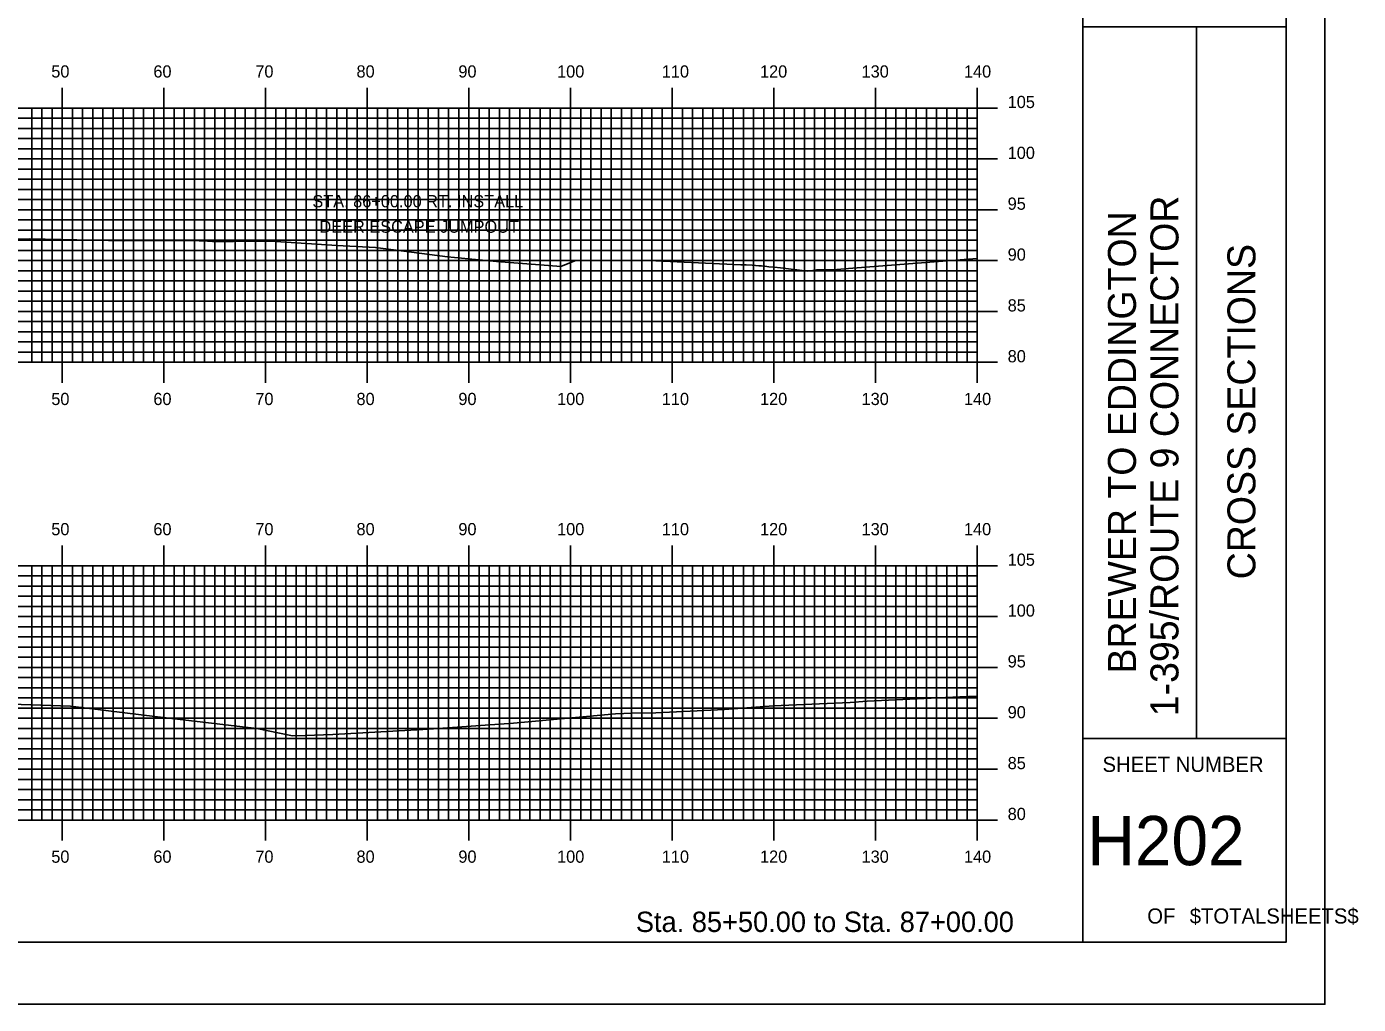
# Model space of a CAD drawing. Extents: x 1763759 to 1764102, y 442591 to 442811.
# Drawn here: x 1763970.8 to 1764101.8, y 442590.5 to 442686.7 of the extents above; entities that cross this region are included whole.
import ezdxf

# ---------------------------------------------------------------- set-up
doc = ezdxf.new("R2010")
doc.units = 0
for name, color, linetype in [('BORDER', 7, 'Continuous'), ('D_Text_Standard', 7, 'Continuous'), ('H_V ANNOTATION', 7, 'Continuous'), ('MAJOR', 7, 'Continuous'), ('MINOR', 7, 'Continuous'), ('PLOT BOUNDARY', 7, 'Continuous'), ('S_Roadway_Centerline', 7, 'Continuous')]:
    doc.layers.add(name, color=color, linetype=linetype)

msp = doc.modelspace()

# ---------------------------------------------------------------- linework, layer by layer
at = {"layer": 'BORDER'}
for p, q in [((1764074.72, 442596.67), (1764074.72, 442806.67)), ((1764074.72, 442686.67), (1764094.72, 442686.67)), ((1764085.9, 442616.67), (1764085.9, 442686.67)), ((1764074.72, 442616.67), (1764094.72, 442616.67))]:
    msp.add_line(p, q, dxfattribs=at)
msp.add_lwpolyline([(1763774.72, 442596.67), (1764094.72, 442596.67), (1764094.72, 442806.67), (1763774.72, 442806.67)], close=True, dxfattribs=at)
at = {"layer": 'MAJOR'}
for p, q in [((1763974.32, 442680.67), (1763974.32, 442678.67)), ((1763984.32, 442680.67), (1763984.32, 442678.67)), ((1763994.32, 442680.67), (1763994.32, 442678.67)), ((1764004.32, 442680.67), (1764004.32, 442678.67)), ((1764014.32, 442680.67), (1764014.32, 442678.67)), ((1764024.32, 442680.67), (1764024.32, 442678.67)), ((1764034.32, 442680.67), (1764034.32, 442678.67)), ((1764044.32, 442680.67), (1764044.32, 442678.67)), ((1764054.32, 442680.67), (1764054.32, 442678.67)), ((1764064.32, 442680.67), (1764064.32, 442678.67)), ((1763784.32, 442678.67), (1764064.32, 442678.67)), ((1763784.32, 442678.67), (1764064.32, 442678.67)), ((1763974.32, 442653.67), (1763974.32, 442678.67)), ((1763984.32, 442653.67), (1763984.32, 442678.67)), ((1763994.32, 442653.67), (1763994.32, 442678.67)), ((1764004.32, 442653.67), (1764004.32, 442678.67)), ((1764014.32, 442653.67), (1764014.32, 442678.67)), ((1764024.32, 442653.67), (1764024.32, 442678.67)), ((1764034.32, 442653.67), (1764034.32, 442678.67)), ((1764044.32, 442653.67), (1764044.32, 442678.67)), ((1764054.32, 442653.67), (1764054.32, 442678.67)), ((1764066.32, 442678.67), (1764062.31, 442678.67)), ((1764064.32, 442653.67), (1764064.32, 442678.67)), ((1764064.32, 442653.67), (1764064.32, 442678.67)), ((1763784.32, 442673.67), (1764064.32, 442673.67)), ((1764066.32, 442673.67), (1764062.31, 442673.67)), ((1763784.32, 442668.67), (1764064.32, 442668.67)), ((1764066.32, 442668.67), (1764062.31, 442668.67)), ((1763784.32, 442663.67), (1764064.32, 442663.67)), ((1764066.32, 442663.67), (1764062.31, 442663.67)), ((1763784.32, 442658.67), (1764064.32, 442658.67)), ((1764066.32, 442658.67), (1764062.31, 442658.67)), ((1763784.32, 442653.67), (1764064.32, 442653.67)), ((1763784.32, 442653.67), (1764064.32, 442653.67)), ((1763974.32, 442651.66), (1763974.32, 442653.67)), ((1763984.32, 442651.66), (1763984.32, 442653.67)), ((1763994.32, 442651.66), (1763994.32, 442653.67)), ((1764004.32, 442651.66), (1764004.32, 442653.67)), ((1764014.32, 442651.66), (1764014.32, 442653.67)), ((1764024.32, 442651.66), (1764024.32, 442653.67)), ((1764034.32, 442651.66), (1764034.32, 442653.67)), ((1764044.32, 442651.66), (1764044.32, 442653.67)), ((1764054.32, 442651.66), (1764054.32, 442653.67)), ((1764066.32, 442653.67), (1764062.31, 442653.67)), ((1764064.32, 442651.66), (1764064.32, 442653.67)), ((1763974.32, 442635.67), (1763974.32, 442633.67)), ((1763984.32, 442635.67), (1763984.32, 442633.67)), ((1763994.32, 442635.67), (1763994.32, 442633.67)), ((1764004.32, 442635.67), (1764004.32, 442633.67)), ((1764014.32, 442635.67), (1764014.32, 442633.67)), ((1764024.32, 442635.67), (1764024.32, 442633.67)), ((1764034.32, 442635.67), (1764034.32, 442633.67)), ((1764044.32, 442635.67), (1764044.32, 442633.67)), ((1764054.32, 442635.67), (1764054.32, 442633.67)), ((1764064.32, 442635.67), (1764064.32, 442633.67)), ((1763784.32, 442633.67), (1764064.32, 442633.67)), ((1763784.32, 442633.67), (1764064.32, 442633.67)), ((1763974.32, 442608.67), (1763974.32, 442633.67)), ((1763984.32, 442608.67), (1763984.32, 442633.67)), ((1763994.32, 442608.67), (1763994.32, 442633.67)), ((1764004.32, 442608.67), (1764004.32, 442633.67)), ((1764014.32, 442608.67), (1764014.32, 442633.67)), ((1764024.32, 442608.67), (1764024.32, 442633.67)), ((1764034.32, 442608.67), (1764034.32, 442633.67)), ((1764044.32, 442608.67), (1764044.32, 442633.67)), ((1764054.32, 442608.67), (1764054.32, 442633.67)), ((1764066.32, 442633.67), (1764062.31, 442633.67)), ((1764064.32, 442608.67), (1764064.32, 442633.67)), ((1764064.32, 442608.67), (1764064.32, 442633.67)), ((1763784.32, 442628.67), (1764064.32, 442628.67)), ((1764066.32, 442628.67), (1764062.31, 442628.67)), ((1763784.32, 442623.67), (1764064.32, 442623.67)), ((1764066.32, 442623.67), (1764062.31, 442623.67)), ((1763784.32, 442618.67), (1764064.32, 442618.67)), ((1764066.32, 442618.67), (1764062.31, 442618.67)), ((1763784.32, 442613.67), (1764064.32, 442613.67)), ((1764066.32, 442613.67), (1764062.31, 442613.67)), ((1763784.32, 442608.67), (1764064.32, 442608.67)), ((1763784.32, 442608.67), (1764064.32, 442608.67)), ((1763974.32, 442606.66), (1763974.32, 442608.67)), ((1763984.32, 442606.66), (1763984.32, 442608.67)), ((1763994.32, 442606.66), (1763994.32, 442608.67)), ((1764004.32, 442606.66), (1764004.32, 442608.67)), ((1764014.32, 442606.66), (1764014.32, 442608.67)), ((1764024.32, 442606.66), (1764024.32, 442608.67)), ((1764034.32, 442606.66), (1764034.32, 442608.67)), ((1764044.32, 442606.66), (1764044.32, 442608.67)), ((1764054.32, 442606.66), (1764054.32, 442608.67)), ((1764066.32, 442608.67), (1764062.31, 442608.67)), ((1764064.32, 442606.66), (1764064.32, 442608.67))]:
    msp.add_line(p, q, dxfattribs=at)
at = {"layer": 'MINOR'}
for p, q in [((1763971.32, 442653.67), (1763971.32, 442678.67)), ((1763972.32, 442653.67), (1763972.32, 442678.67)), ((1763973.32, 442653.67), (1763973.32, 442678.67)), ((1763975.32, 442653.67), (1763975.32, 442678.67)), ((1763976.32, 442653.67), (1763976.32, 442678.67)), ((1763977.32, 442653.67), (1763977.32, 442678.67)), ((1763978.32, 442653.67), (1763978.32, 442678.67)), ((1763979.32, 442653.67), (1763979.32, 442678.67)), ((1763980.32, 442653.67), (1763980.32, 442678.67)), ((1763981.32, 442653.67), (1763981.32, 442678.67)), ((1763982.32, 442653.67), (1763982.32, 442678.67)), ((1763983.32, 442653.67), (1763983.32, 442678.67)), ((1763985.32, 442653.67), (1763985.32, 442678.67)), ((1763986.32, 442653.67), (1763986.32, 442678.67)), ((1763987.32, 442653.67), (1763987.32, 442678.67)), ((1763988.32, 442653.67), (1763988.32, 442678.67)), ((1763989.32, 442653.67), (1763989.32, 442678.67)), ((1763990.32, 442653.67), (1763990.32, 442678.67)), ((1763991.32, 442653.67), (1763991.32, 442678.67)), ((1763992.32, 442653.67), (1763992.32, 442678.67)), ((1763993.32, 442653.67), (1763993.32, 442678.67)), ((1763995.32, 442653.67), (1763995.32, 442678.67)), ((1763996.32, 442653.67), (1763996.32, 442678.67)), ((1763997.32, 442653.67), (1763997.32, 442678.67)), ((1763998.32, 442653.67), (1763998.32, 442678.67)), ((1763999.32, 442653.67), (1763999.32, 442678.67)), ((1764000.32, 442653.67), (1764000.32, 442678.67)), ((1764001.32, 442653.67), (1764001.32, 442678.67)), ((1764002.32, 442653.67), (1764002.32, 442678.67)), ((1764003.32, 442653.67), (1764003.32, 442678.67)), ((1764005.32, 442653.67), (1764005.32, 442678.67)), ((1764006.32, 442653.67), (1764006.32, 442678.67)), ((1764007.32, 442653.67), (1764007.32, 442678.67)), ((1764008.32, 442653.67), (1764008.32, 442678.67)), ((1764009.32, 442653.67), (1764009.32, 442678.67)), ((1764010.32, 442653.67), (1764010.32, 442678.67)), ((1764011.32, 442653.67), (1764011.32, 442678.67)), ((1764012.32, 442653.67), (1764012.32, 442678.67)), ((1764013.32, 442653.67), (1764013.32, 442678.67)), ((1764015.32, 442653.67), (1764015.32, 442678.67)), ((1764016.32, 442653.67), (1764016.32, 442678.67)), ((1764017.32, 442653.67), (1764017.32, 442678.67)), ((1764018.32, 442653.67), (1764018.32, 442678.67)), ((1764019.32, 442653.67), (1764019.32, 442678.67)), ((1764020.32, 442653.67), (1764020.32, 442678.67)), ((1764021.32, 442653.67), (1764021.32, 442678.67)), ((1764022.32, 442653.67), (1764022.32, 442678.67)), ((1764023.32, 442653.67), (1764023.32, 442678.67)), ((1764025.32, 442653.67), (1764025.32, 442678.67)), ((1764026.32, 442653.67), (1764026.32, 442678.67)), ((1764027.32, 442653.67), (1764027.32, 442678.67)), ((1764028.32, 442653.67), (1764028.32, 442678.67)), ((1764029.32, 442653.67), (1764029.32, 442678.67)), ((1764030.32, 442653.67), (1764030.32, 442678.67)), ((1764031.32, 442653.67), (1764031.32, 442678.67)), ((1764032.32, 442653.67), (1764032.32, 442678.67)), ((1764033.32, 442653.67), (1764033.32, 442678.67)), ((1764035.32, 442653.67), (1764035.32, 442678.67)), ((1764036.32, 442653.67), (1764036.32, 442678.67)), ((1764037.32, 442653.67), (1764037.32, 442678.67)), ((1764038.32, 442653.67), (1764038.32, 442678.67)), ((1764039.32, 442653.67), (1764039.32, 442678.67)), ((1764040.32, 442653.67), (1764040.32, 442678.67)), ((1764041.32, 442653.67), (1764041.32, 442678.67)), ((1764042.32, 442653.67), (1764042.32, 442678.67)), ((1764043.32, 442653.67), (1764043.32, 442678.67)), ((1764045.32, 442653.67), (1764045.32, 442678.67)), ((1764046.32, 442653.67), (1764046.32, 442678.67)), ((1764047.32, 442653.67), (1764047.32, 442678.67)), ((1764048.32, 442653.67), (1764048.32, 442678.67)), ((1764049.32, 442653.67), (1764049.32, 442678.67)), ((1764050.32, 442653.67), (1764050.32, 442678.67)), ((1764051.32, 442653.67), (1764051.32, 442678.67)), ((1764052.32, 442653.67), (1764052.32, 442678.67)), ((1764053.32, 442653.67), (1764053.32, 442678.67)), ((1764055.32, 442653.67), (1764055.32, 442678.67)), ((1764056.32, 442653.67), (1764056.32, 442678.67)), ((1764057.32, 442653.67), (1764057.32, 442678.67)), ((1764058.32, 442653.67), (1764058.32, 442678.67)), ((1764059.32, 442653.67), (1764059.32, 442678.67)), ((1764060.32, 442653.67), (1764060.32, 442678.67)), ((1764061.32, 442653.67), (1764061.32, 442678.67)), ((1764062.32, 442653.67), (1764062.32, 442678.67)), ((1764063.32, 442653.67), (1764063.32, 442678.67)), ((1763784.32, 442677.67), (1764064.32, 442677.67)), ((1764064.32, 442677.67), (1764062.31, 442677.67)), ((1763784.32, 442676.67), (1764064.32, 442676.67)), ((1763784.32, 442675.67), (1764064.32, 442675.67)), ((1764064.32, 442676.67), (1764062.31, 442676.67)), ((1764064.32, 442675.67), (1764062.31, 442675.67)), ((1763784.32, 442674.67), (1764064.32, 442674.67)), ((1764064.32, 442674.67), (1764062.31, 442674.67)), ((1763784.32, 442672.67), (1764064.32, 442672.67)), ((1763784.32, 442671.67), (1764064.32, 442671.67)), ((1764064.32, 442672.67), (1764062.31, 442672.67)), ((1764064.32, 442671.67), (1764062.31, 442671.67)), ((1763784.32, 442670.67), (1764064.32, 442670.67)), ((1764064.32, 442670.67), (1764062.31, 442670.67)), ((1763784.32, 442669.67), (1764064.32, 442669.67)), ((1764064.32, 442669.67), (1764062.31, 442669.67)), ((1763784.32, 442667.67), (1764064.32, 442667.67)), ((1763784.32, 442666.67), (1764064.32, 442666.67)), ((1764064.32, 442667.67), (1764062.31, 442667.67)), ((1764064.32, 442666.67), (1764062.31, 442666.67)), ((1763784.32, 442665.67), (1764064.32, 442665.67)), ((1764064.32, 442665.67), (1764062.31, 442665.67)), ((1763784.32, 442664.67), (1764064.32, 442664.67)), ((1764064.32, 442664.67), (1764062.31, 442664.67)), ((1763784.32, 442662.67), (1764064.32, 442662.67)), ((1764064.32, 442662.67), (1764062.31, 442662.67)), ((1763784.32, 442661.67), (1764064.32, 442661.67)), ((1764064.32, 442661.67), (1764062.31, 442661.67)), ((1763784.32, 442660.67), (1764064.32, 442660.67)), ((1764064.32, 442660.67), (1764062.31, 442660.67)), ((1763784.32, 442659.67), (1764064.32, 442659.67)), ((1764064.32, 442659.67), (1764062.31, 442659.67)), ((1763784.32, 442657.67), (1764064.32, 442657.67)), ((1764064.32, 442657.67), (1764062.31, 442657.67)), ((1763784.32, 442656.67), (1764064.32, 442656.67)), ((1764064.32, 442656.67), (1764062.31, 442656.67)), ((1763784.32, 442655.67), (1764064.32, 442655.67)), ((1763784.32, 442654.67), (1764064.32, 442654.67)), ((1764064.32, 442655.67), (1764062.31, 442655.67)), ((1764064.32, 442654.67), (1764062.31, 442654.67)), ((1763971.32, 442608.67), (1763971.32, 442633.67)), ((1763972.32, 442608.67), (1763972.32, 442633.67)), ((1763973.32, 442608.67), (1763973.32, 442633.67)), ((1763975.32, 442608.67), (1763975.32, 442633.67)), ((1763976.32, 442608.67), (1763976.32, 442633.67)), ((1763977.32, 442608.67), (1763977.32, 442633.67)), ((1763978.32, 442608.67), (1763978.32, 442633.67)), ((1763979.32, 442608.67), (1763979.32, 442633.67)), ((1763980.32, 442608.67), (1763980.32, 442633.67)), ((1763981.32, 442608.67), (1763981.32, 442633.67)), ((1763982.32, 442608.67), (1763982.32, 442633.67)), ((1763983.32, 442608.67), (1763983.32, 442633.67)), ((1763985.32, 442608.67), (1763985.32, 442633.67)), ((1763986.32, 442608.67), (1763986.32, 442633.67)), ((1763987.32, 442608.67), (1763987.32, 442633.67)), ((1763988.32, 442608.67), (1763988.32, 442633.67)), ((1763989.32, 442608.67), (1763989.32, 442633.67)), ((1763990.32, 442608.67), (1763990.32, 442633.67)), ((1763991.32, 442608.67), (1763991.32, 442633.67)), ((1763992.32, 442608.67), (1763992.32, 442633.67)), ((1763993.32, 442608.67), (1763993.32, 442633.67)), ((1763995.32, 442608.67), (1763995.32, 442633.67)), ((1763996.32, 442608.67), (1763996.32, 442633.67)), ((1763997.32, 442608.67), (1763997.32, 442633.67)), ((1763998.32, 442608.67), (1763998.32, 442633.67)), ((1763999.32, 442608.67), (1763999.32, 442633.67)), ((1764000.32, 442608.67), (1764000.32, 442633.67)), ((1764001.32, 442608.67), (1764001.32, 442633.67)), ((1764002.32, 442608.67), (1764002.32, 442633.67)), ((1764003.32, 442608.67), (1764003.32, 442633.67)), ((1764005.32, 442608.67), (1764005.32, 442633.67)), ((1764006.32, 442608.67), (1764006.32, 442633.67)), ((1764007.32, 442608.67), (1764007.32, 442633.67)), ((1764008.32, 442608.67), (1764008.32, 442633.67)), ((1764009.32, 442608.67), (1764009.32, 442633.67)), ((1764010.32, 442608.67), (1764010.32, 442633.67)), ((1764011.32, 442608.67), (1764011.32, 442633.67)), ((1764012.32, 442608.67), (1764012.32, 442633.67)), ((1764013.32, 442608.67), (1764013.32, 442633.67)), ((1764015.32, 442608.67), (1764015.32, 442633.67)), ((1764016.32, 442608.67), (1764016.32, 442633.67)), ((1764017.32, 442608.67), (1764017.32, 442633.67)), ((1764018.32, 442608.67), (1764018.32, 442633.67)), ((1764019.32, 442608.67), (1764019.32, 442633.67)), ((1764020.32, 442608.67), (1764020.32, 442633.67)), ((1764021.32, 442608.67), (1764021.32, 442633.67)), ((1764022.32, 442608.67), (1764022.32, 442633.67)), ((1764023.32, 442608.67), (1764023.32, 442633.67)), ((1764025.32, 442608.67), (1764025.32, 442633.67)), ((1764026.32, 442608.67), (1764026.32, 442633.67)), ((1764027.32, 442608.67), (1764027.32, 442633.67)), ((1764028.32, 442608.67), (1764028.32, 442633.67)), ((1764029.32, 442608.67), (1764029.32, 442633.67)), ((1764030.32, 442608.67), (1764030.32, 442633.67)), ((1764031.32, 442608.67), (1764031.32, 442633.67)), ((1764032.32, 442608.67), (1764032.32, 442633.67)), ((1764033.32, 442608.67), (1764033.32, 442633.67)), ((1764035.32, 442608.67), (1764035.32, 442633.67)), ((1764036.32, 442608.67), (1764036.32, 442633.67)), ((1764037.32, 442608.67), (1764037.32, 442633.67)), ((1764038.32, 442608.67), (1764038.32, 442633.67)), ((1764039.32, 442608.67), (1764039.32, 442633.67)), ((1764040.32, 442608.67), (1764040.32, 442633.67)), ((1764041.32, 442608.67), (1764041.32, 442633.67)), ((1764042.32, 442608.67), (1764042.32, 442633.67)), ((1764043.32, 442608.67), (1764043.32, 442633.67)), ((1764045.32, 442608.67), (1764045.32, 442633.67)), ((1764046.32, 442608.67), (1764046.32, 442633.67)), ((1764047.32, 442608.67), (1764047.32, 442633.67)), ((1764048.32, 442608.67), (1764048.32, 442633.67)), ((1764049.32, 442608.67), (1764049.32, 442633.67)), ((1764050.32, 442608.67), (1764050.32, 442633.67)), ((1764051.32, 442608.67), (1764051.32, 442633.67)), ((1764052.32, 442608.67), (1764052.32, 442633.67)), ((1764053.32, 442608.67), (1764053.32, 442633.67)), ((1764055.32, 442608.67), (1764055.32, 442633.67)), ((1764056.32, 442608.67), (1764056.32, 442633.67)), ((1764057.32, 442608.67), (1764057.32, 442633.67)), ((1764058.32, 442608.67), (1764058.32, 442633.67)), ((1764059.32, 442608.67), (1764059.32, 442633.67)), ((1764060.32, 442608.67), (1764060.32, 442633.67)), ((1764061.32, 442608.67), (1764061.32, 442633.67)), ((1764062.32, 442608.67), (1764062.32, 442633.67)), ((1764063.32, 442608.67), (1764063.32, 442633.67)), ((1763784.32, 442632.67), (1764064.32, 442632.67)), ((1764064.32, 442632.67), (1764062.31, 442632.67)), ((1763784.32, 442631.67), (1764064.32, 442631.67)), ((1764064.32, 442631.67), (1764062.31, 442631.67)), ((1763784.32, 442630.67), (1764064.32, 442630.67)), ((1764064.32, 442630.67), (1764062.31, 442630.67)), ((1763784.32, 442629.67), (1764064.32, 442629.67)), ((1764064.32, 442629.67), (1764062.31, 442629.67)), ((1763784.32, 442627.67), (1764064.32, 442627.67)), ((1764064.32, 442627.67), (1764062.31, 442627.67)), ((1763784.32, 442626.67), (1764064.32, 442626.67)), ((1764064.32, 442626.67), (1764062.31, 442626.67)), ((1763784.32, 442625.67), (1764064.32, 442625.67)), ((1763784.32, 442624.67), (1764064.32, 442624.67)), ((1764064.32, 442625.67), (1764062.31, 442625.67)), ((1764064.32, 442624.67), (1764062.31, 442624.67)), ((1763784.32, 442622.67), (1764064.32, 442622.67)), ((1764064.32, 442622.67), (1764062.31, 442622.67)), ((1763784.32, 442621.67), (1764064.32, 442621.67)), ((1763784.32, 442620.67), (1764064.32, 442620.67)), ((1764064.32, 442621.67), (1764062.31, 442621.67)), ((1764064.32, 442620.67), (1764062.31, 442620.67)), ((1763784.32, 442619.67), (1764064.32, 442619.67)), ((1764064.32, 442619.67), (1764062.31, 442619.67)), ((1763784.32, 442617.67), (1764064.32, 442617.67)), ((1763784.32, 442616.67), (1764064.32, 442616.67)), ((1764064.32, 442617.67), (1764062.31, 442617.67)), ((1764064.32, 442616.67), (1764062.31, 442616.67)), ((1763784.32, 442615.67), (1764064.32, 442615.67)), ((1764064.32, 442615.67), (1764062.31, 442615.67)), ((1763784.32, 442614.67), (1764064.32, 442614.67)), ((1764064.32, 442614.67), (1764062.31, 442614.67)), ((1763784.32, 442612.67), (1764064.32, 442612.67)), ((1764064.32, 442612.67), (1764062.31, 442612.67)), ((1763784.32, 442611.67), (1764064.32, 442611.67)), ((1764064.32, 442611.67), (1764062.31, 442611.67)), ((1763784.32, 442610.67), (1764064.32, 442610.67)), ((1764064.32, 442610.67), (1764062.31, 442610.67)), ((1763784.32, 442609.67), (1764064.32, 442609.67)), ((1764064.32, 442609.67), (1764062.31, 442609.67))]:
    msp.add_line(p, q, dxfattribs=at)
at = {"layer": 'PLOT BOUNDARY'}
msp.add_lwpolyline([(1763758.53, 442590.55), (1764098.53, 442590.55), (1764098.53, 442810.55), (1763758.53, 442810.55)], close=True, dxfattribs=at)
at = {"layer": 'S_Roadway_Centerline'}
for points in [[(1763954.72, 442665.75), (1763971.09, 442665.8), (1763980.44, 442665.61), (1763986.98, 442665.64), (1763988.61, 442665.57), (1763989.1, 442665.55), (1763989.79, 442665.56), (1763991.18, 442665.56), (1763994.86, 442665.59), (1764001.35, 442665.17), (1764005.13, 442664.96), (1764012.22, 442664.04), (1764017.05, 442663.58), (1764022.17, 442663.18), (1764023.38, 442663.09), (1764023.91, 442663.31), (1764024.85, 442663.69), (1764031.33, 442663.73), (1764041.08, 442663.27), (1764041.61, 442663.24), (1764042.2, 442663.21), (1764042.84, 442663.17), (1764043.11, 442663.15), (1764043.44, 442663.11), (1764043.84, 442663.07), (1764044.34, 442663.02), (1764044.96, 442662.95), (1764045.77, 442662.85), (1764046.83, 442662.72), (1764047.65, 442662.62), (1764048.06, 442662.68), (1764048.3, 442662.72), (1764048.51, 442662.75), (1764050.52, 442662.8), (1764051.66, 442662.88), (1764064.32, 442663.87)], [(1763960.52, 442620.37), (1763975.15, 442619.87), (1763983.7, 442618.81), (1763993.48, 442617.66), (1763996.82, 442616.99), (1763996.99, 442616.96), (1763998.22, 442616.99), (1764000.93, 442617.08), (1764010.37, 442617.59), (1764018.7, 442618.19), (1764028.75, 442619.11), (1764030.4, 442619.17), (1764032.71, 442619.21), (1764039.47, 442619.55), (1764044.28, 442619.89), (1764046.55, 442620.01), (1764051.84, 442620.24), (1764053.5, 442620.36), (1764062.6, 442620.78), (1764064.32, 442620.86)]]:
    msp.add_lwpolyline(points, dxfattribs=at)

# ---------------------------------------------------------------- texts
at = {"layer": 'BORDER'}
for s, p in [('1-395/ROUTE 9 CONNECTOR', (1764084.12, 442618.87)), ('BREWER TO EDDINGTON', (1764079.94, 442623.07)), ('CROSS SECTIONS', (1764091.69, 442632.34))]:
    msp.add_text(s, height=2.7557, rotation=90, dxfattribs=at).set_placement(p)
for s, height, p in [('SHEET NUMBER', 1.4905, (1764076.65, 442613.4)), ('H202', 4.839, (1764075.16, 442604.23)), ('OF', 1.491, (1764081.05, 442598.49)), ('$TOTALSHEETS$', 1.4905, (1764085.23, 442598.49))]:
    msp.add_text(s, height=height, dxfattribs=at).set_placement(p)
at = {"layer": 'D_Text_Standard'}
for s, p in [('STA. 86+00.00 RT. INSTALL ', (1763998.93, 442668.91)), ('DEER ESCAPE JUMPOUT', (1763999.63, 442666.41))]:
    msp.add_text(s, height=1.2, dxfattribs=at).set_placement(p)
at = {"layer": 'H_V ANNOTATION'}
for s, height, p in [('50', 1.2, (1763973.25, 442681.67)), ('60', 1.2, (1763983.29, 442681.67)), ('70', 1.2, (1763993.32, 442681.67)), ('80', 1.2, (1764003.27, 442681.67)), ('90', 1.2, (1764013.29, 442681.67)), ('100', 1.2, (1764023, 442681.67)), ('110', 1.2, (1764033.3, 442681.67)), ('120', 1.2, (1764042.96, 442681.67)), ('130', 1.2, (1764052.95, 442681.67)), ('140', 1.2, (1764063.02, 442681.67)), ('105', 1.2, (1764067.32, 442678.67)), ('100', 1.2, (1764067.32, 442673.67)), ('95', 1.2, (1764067.32, 442668.67)), ('90', 1.2, (1764067.32, 442663.67)), ('85', 1.2, (1764067.32, 442658.67)), ('80', 1.2, (1764067.32, 442653.67)), ('50', 1.2, (1763973.25, 442649.47)), ('60', 1.2, (1763983.29, 442649.47)), ('70', 1.2, (1763993.32, 442649.47)), ('80', 1.2, (1764003.27, 442649.47)), ('90', 1.2, (1764013.29, 442649.47)), ('100', 1.2, (1764023, 442649.47)), ('110', 1.2, (1764033.3, 442649.47)), ('120', 1.2, (1764042.96, 442649.47)), ('130', 1.2, (1764052.95, 442649.47)), ('140', 1.2, (1764063.02, 442649.47)), ('50', 1.2, (1763973.25, 442636.67)), ('60', 1.2, (1763983.29, 442636.67)), ('70', 1.2, (1763993.32, 442636.67)), ('80', 1.2, (1764003.27, 442636.67)), ('90', 1.2, (1764013.29, 442636.67)), ('100', 1.2, (1764023, 442636.67)), ('110', 1.2, (1764033.3, 442636.67)), ('120', 1.2, (1764042.96, 442636.67)), ('130', 1.2, (1764052.95, 442636.67)), ('140', 1.2, (1764063.02, 442636.67)), ('105', 1.2, (1764067.32, 442633.67)), ('100', 1.2, (1764067.32, 442628.67)), ('95', 1.2, (1764067.32, 442623.67)), ('90', 1.2, (1764067.32, 442618.67)), ('85', 1.2, (1764067.32, 442613.67)), ('80', 1.2, (1764067.32, 442608.67)), ('50', 1.2, (1763973.25, 442604.47)), ('60', 1.2, (1763983.29, 442604.47)), ('70', 1.2, (1763993.32, 442604.47)), ('80', 1.2, (1764003.27, 442604.47)), ('90', 1.2, (1764013.29, 442604.47)), ('100', 1.2, (1764023, 442604.47)), ('110', 1.2, (1764033.3, 442604.47)), ('120', 1.2, (1764042.96, 442604.47)), ('130', 1.2, (1764052.95, 442604.47)), ('140', 1.2, (1764063.02, 442604.47)), ('Sta. 85+50.00 to Sta. 87+00.00', 2.0004, (1764030.75, 442597.66))]:
    msp.add_text(s, height=height, dxfattribs=at).set_placement(p)

doc.saveas('drawing.dxf')
